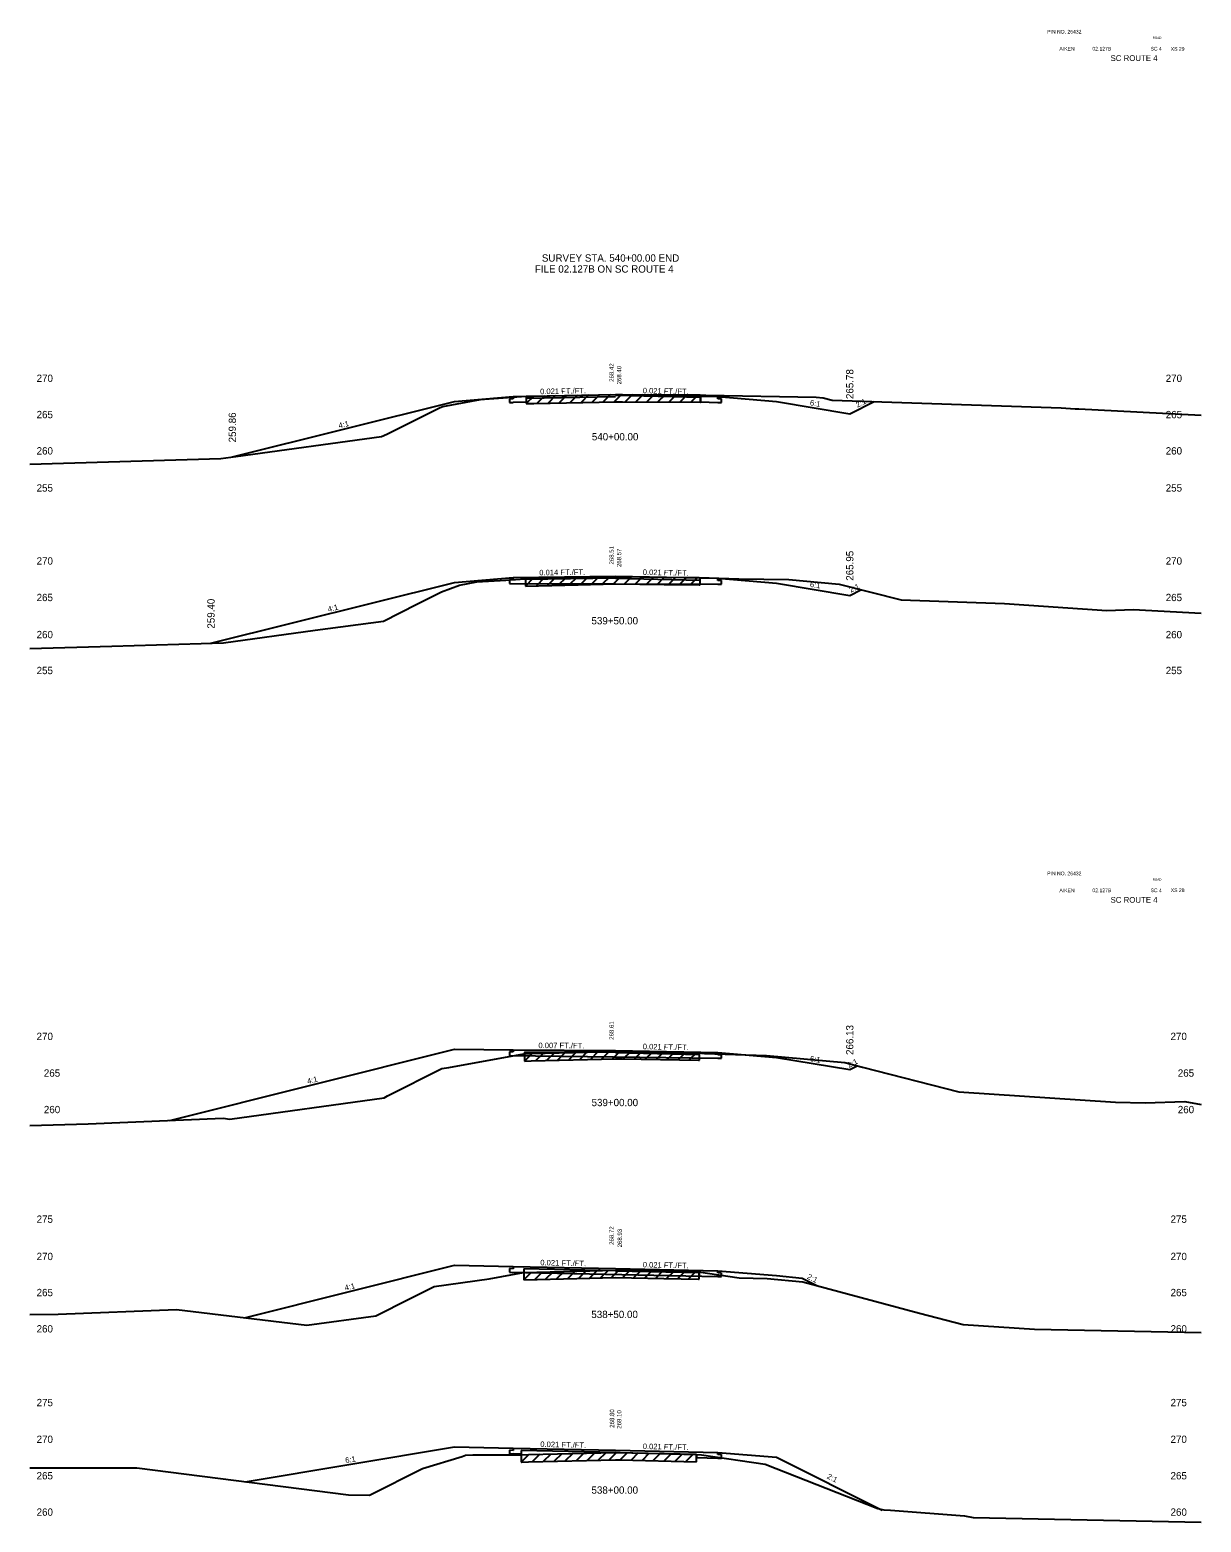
# Model space of a CAD drawing. Extents: x 883 to 1160, y 1002 to 4323.
# Drawn here: x 1000 to 1160, y 4119.3 to 4323.2 of the extents above; entities that cross this region are included whole.
import ezdxf

# ---------------------------------------------------------------- set-up
doc = ezdxf.new("R2010")
doc.units = 0
for name, color, linetype in [('Level 1', 7, 'Continuous'), ('Level 10', 7, 'Continuous'), ('Level 11', 7, 'Continuous'), ('Level 12', 7, 'Continuous'), ('Level 3', 7, 'Continuous'), ('Level 32', 7, 'Continuous'), ('Level 33', 7, 'Continuous'), ('Level 53', 7, 'Continuous'), ('Level 59', 7, 'Continuous'), ('Level 6', 7, 'Continuous'), ('Level 60', 7, 'Continuous'), ('Level 61', 7, 'Continuous'), ('Level 7', 7, 'Continuous')]:
    doc.layers.add(name, color=color, linetype=linetype)

msp = doc.modelspace()

# ---------------------------------------------------------------- linework, layer by layer
at = {"layer": 'Level 11'}
for p, q in [((1066, 4272.81), (1065.5, 4272.8)), ((1065.5, 4272.8), (1065.5, 4272.32)), ((1065.5, 4272.32), (1066, 4272.33)), ((1066, 4273.11), (1066, 4272.81)), ((1094, 4272.81), (1094, 4273.11)), ((1094.5, 4272.8), (1094, 4272.81)), ((1094, 4272.33), (1094.5, 4272.32)), ((1094.5, 4272.32), (1094.5, 4272.8)), ((1066, 4248.08), (1065.5, 4248.07)), ((1065.5, 4248.07), (1065.5, 4247.59)), ((1066, 4248.38), (1066, 4248.08)), ((1094, 4247.98), (1094, 4248.28)), ((1094.5, 4247.97), (1094, 4247.98)), ((1094, 4247.5), (1094.5, 4247.49)), ((1094.5, 4247.49), (1094.5, 4247.97)), ((1066, 4183.54), (1065.5, 4183.55)), ((1065.5, 4183.55), (1065.5, 4183.07)), ((1066, 4183.84), (1066, 4183.54)), ((1094, 4183.16), (1094, 4183.46)), ((1094.5, 4183.15), (1094, 4183.16)), ((1094, 4182.68), (1094.5, 4182.67)), ((1094.5, 4182.67), (1094.5, 4183.15)), ((1066, 4153.92), (1065.5, 4153.93)), ((1065.5, 4153.93), (1065.5, 4153.45)), ((1066, 4154.22), (1066, 4153.92)), ((1094, 4153.33), (1094, 4153.63)), ((1094.5, 4153.32), (1094, 4153.33)), ((1094, 4152.85), (1094.5, 4152.84)), ((1094.5, 4152.84), (1094.5, 4153.32)), ((1066, 4129.09), (1065.5, 4129.1)), ((1065.5, 4129.1), (1065.5, 4128.62)), ((1065.5, 4128.62), (1066, 4128.61)), ((1066, 4129.39), (1066, 4129.09)), ((1094, 4128.51), (1094, 4128.81)), ((1094.5, 4128.5), (1094, 4128.51)), ((1094.5, 4128.02), (1094.5, 4128.5)), ((1094, 4128.03), (1094.5, 4128.02))]:
    msp.add_line(p, q, dxfattribs=at)
at = {"layer": 'Level 12'}
for p, q in [((1067.8, 4273.16), (1067.8, 4272.37)), ((1091.61, 4273.35), (1091.61, 4272.38)), ((1067.8, 4272.37), (1066, 4272.33)), ((1091.61, 4272.38), (1094, 4272.33)), ((1065.5, 4247.59), (1094, 4247.5)), ((1065.5, 4183.07), (1094, 4182.68)), ((1065.5, 4153.45), (1094, 4152.85)), ((1067.46, 4153.4), (1067.46, 4153.41)), ((1091.41, 4153.48), (1091.41, 4152.91)), ((1067.13, 4128.59), (1066, 4128.61)), ((1067.13, 4128.49), (1067.13, 4128.59)), ((1091.08, 4128.54), (1091.08, 4128.09)), ((1091.08, 4128.09), (1094, 4128.03))]:
    msp.add_line(p, q, dxfattribs=at)
at = {"layer": 'Level 53'}
for p, q in [((1080, 4273.29), (1091.61, 4273.05)), ((1080, 4273.1), (1067.8, 4272.85)), ((1080, 4248.28), (1067.69, 4248.1)), ((1080, 4248.28), (1091.55, 4248.03)), ((1080, 4183.45), (1067.57, 4183.53)), ((1067.57, 4183.53), (1067.57, 4183.29)), ((1080, 4183.45), (1091.48, 4183.21)), ((1080, 4153.63), (1067.46, 4153.89)), ((1067.46, 4153.89), (1067.46, 4153.4)), ((1080, 4153.63), (1091.41, 4153.39)), ((1080, 4128.8), (1067.13, 4129.07)), ((1067.13, 4129.07), (1067.13, 4128.49)), ((1080, 4128.8), (1091.08, 4128.57)), ((1091.08, 4128.57), (1091.08, 4128.54))]:
    msp.add_line(p, q, dxfattribs=at)
at = {"layer": 'Level 59'}
for p, q in [((1066, 4273.11), (1080, 4273.4)), ((1080, 4273.4), (1094, 4273.11)), ((1066, 4248.38), (1080, 4248.58)), ((1080, 4248.58), (1094, 4248.28)), ((1066, 4183.84), (1080, 4183.75)), ((1080, 4183.75), (1094, 4183.46)), ((1066, 4154.22), (1080, 4153.93)), ((1080, 4153.93), (1094, 4153.63)), ((1066, 4129.39), (1080, 4129.1)), ((1080, 4129.1), (1094, 4128.81))]:
    msp.add_line(p, q, dxfattribs=at)
at = {"layer": 'Level 6'}
for p, q in [((1058, 4272.44), (1066, 4273.11)), ((1094, 4273.11), (1102, 4272.44)), ((1058, 4247.71), (1066, 4248.38)), ((1094, 4248.28), (1102, 4247.62)), ((1058, 4183.9), (1066, 4183.84)), ((1094, 4183.46), (1102, 4182.79)), ((1058, 4154.38), (1066, 4154.22)), ((1094, 4153.63), (1102, 4152.97)), ((1102, 4152.97), (1105.5, 4152.62)), ((1058, 4129.56), (1066, 4129.39)), ((1094, 4128.81), (1102, 4128.14))]:
    msp.add_line(p, q, dxfattribs=at)
at = {"layer": 'Level 60'}
for p, q in [((1062.12, 4272.78), (1067.8, 4273.16)), ((1067.8, 4273.16), (1068.85, 4273.19)), ((1068.85, 4273.19), (1080.02, 4273.42)), ((1080.02, 4273.42), (1080.96, 4273.4)), ((1080.96, 4273.4), (1091.56, 4273.35)), ((1091.56, 4273.35), (1092.33, 4273.32)), ((1092.33, 4273.32), (1107.41, 4273.03)), ((1048.75, 4268), (1056.03, 4271.64)), ((1056.03, 4271.64), (1056.4, 4271.78)), ((1056.4, 4271.78), (1061.54, 4272.74)), ((1061.54, 4272.74), (1062.12, 4272.78)), ((1107.41, 4273.03), (1108.39, 4272.94)), ((1108.39, 4272.94), (1109.59, 4272.64)), ((1109.59, 4272.64), (1140.87, 4271.57)), ((1140.87, 4271.57), (1142.8, 4271.44)), ((1142.8, 4271.44), (1143.3, 4271.46)), ((1143.3, 4271.46), (1160, 4270.59)), ((1028.15, 4264.92), (1048.05, 4267.64)), ((1048.05, 4267.64), (1048.75, 4268)), ((1000, 4263.89), (1026.08, 4264.64)), ((1026.08, 4264.64), (1028.15, 4264.92)), ((1056.25, 4246.44), (1058.7, 4247.36)), ((1058.7, 4247.36), (1061.06, 4247.8)), ((1061.06, 4247.8), (1065.03, 4248.04)), ((1065.03, 4248.04), (1067.64, 4248.22)), ((1067.64, 4248.22), (1074.91, 4248.41)), ((1074.91, 4248.41), (1080, 4248.51)), ((1080, 4248.51), (1086.64, 4248.42)), ((1086.64, 4248.42), (1091.45, 4248.39)), ((1091.45, 4248.39), (1096.85, 4248.23)), ((1096.85, 4248.23), (1103.68, 4248.1)), ((1103.68, 4248.1), (1110.56, 4247.48)), ((1110.56, 4247.48), (1119.02, 4245.32)), ((1048.3, 4242.44), (1052.88, 4244.75)), ((1052.88, 4244.75), (1056.25, 4246.44)), ((1119.02, 4245.32), (1133.13, 4244.84)), ((1133.13, 4244.84), (1147.14, 4243.9)), ((1147.14, 4243.9), (1150.72, 4244.01)), ((1150.72, 4244.01), (1160, 4243.53)), ((1026.43, 4239.45), (1038.97, 4241.17)), ((1038.97, 4241.17), (1048.3, 4242.44)), ((1000, 4238.69), (1011.18, 4239.01)), ((1011.18, 4239.01), (1026.43, 4239.45)), ((1068.47, 4183.31), (1080, 4183.61)), ((1080, 4183.61), (1080.91, 4183.59)), ((1080.91, 4183.59), (1091.36, 4183.44)), ((1091.36, 4183.44), (1092.16, 4183.32)), ((1056.28, 4181.29), (1057.22, 4181.42)), ((1057.22, 4181.42), (1067.49, 4183.29)), ((1067.49, 4183.29), (1068.47, 4183.31)), ((1092.16, 4183.32), (1100.61, 4183.07)), ((1100.61, 4183.07), (1111.34, 4182.1)), ((1111.34, 4182.1), (1113.72, 4181.45)), ((1113.72, 4181.45), (1126.88, 4178.09)), ((1048.87, 4177.53), (1056.28, 4181.29)), ((1027.33, 4174.36), (1048.39, 4177.28)), ((1048.39, 4177.28), (1048.87, 4177.53)), ((1126.88, 4178.09), (1148.31, 4176.67)), ((1148.31, 4176.67), (1152.35, 4176.59)), ((1152.35, 4176.59), (1157.77, 4176.76)), ((1157.77, 4176.76), (1160, 4176.35)), ((1000, 4173.49), (1007.96, 4173.72)), ((1007.96, 4173.72), (1026.4, 4174.47)), ((1026.4, 4174.47), (1027.33, 4174.36)), ((1062.74, 4152.54), (1067.43, 4153.4)), ((1067.43, 4153.4), (1074.74, 4153.58)), ((1074.74, 4153.58), (1080, 4153.72)), ((1080, 4153.72), (1086.59, 4153.56)), ((1086.59, 4153.56), (1091.34, 4153.49)), ((1091.34, 4153.49), (1096.88, 4152.69)), ((1051.84, 4149.78), (1055.21, 4151.49)), ((1055.21, 4151.49), (1062.74, 4152.54)), ((1096.88, 4152.69), (1100.71, 4152.58)), ((1100.71, 4152.58), (1105.58, 4152.14)), ((1105.58, 4152.14), (1121.52, 4147.82)), ((1047.27, 4147.49), (1051.84, 4149.78)), ((1000, 4147.66), (1003.85, 4147.69)), ((1003.85, 4147.69), (1020.04, 4148.35)), ((1020.04, 4148.35), (1037.82, 4146.18)), ((1037.82, 4146.18), (1047.27, 4147.49)), ((1121.52, 4147.82), (1127.5, 4146.29)), ((1127.5, 4146.29), (1137.24, 4145.65)), ((1137.24, 4145.65), (1160, 4145.19)), ((1059.06, 4128.26), (1059.51, 4128.44)), ((1059.51, 4128.44), (1060.49, 4128.46)), ((1060.49, 4128.46), (1067.15, 4128.49)), ((1067.15, 4128.49), (1068.13, 4128.52)), ((1068.13, 4128.52), (1080, 4128.8)), ((1080, 4128.8), (1080.64, 4128.79)), ((1080.64, 4128.79), (1091.05, 4128.54)), ((1091.05, 4128.54), (1091.77, 4128.47)), ((1091.77, 4128.47), (1100.46, 4127.21)), ((1000, 4126.69), (1013.54, 4126.69)), ((1013.54, 4126.69), (1014.6, 4126.68)), ((1014.6, 4126.68), (1043.54, 4122.99)), ((1046.38, 4122.97), (1053.63, 4126.6)), ((1053.63, 4126.6), (1059.06, 4128.26)), ((1100.46, 4127.21), (1115.83, 4121.16)), ((1043.54, 4122.99), (1046.38, 4122.97)), ((1115.83, 4121.16), (1116.65, 4120.97)), ((1116.65, 4120.97), (1117.58, 4120.93)), ((1117.58, 4120.93), (1127.66, 4120.15)), ((1127.66, 4120.15), (1128.84, 4119.9)), ((1128.84, 4119.9), (1160, 4119.27))]:
    msp.add_line(p, q, dxfattribs=at)
at = {"layer": 'Level 61'}
for p, q in [((1068.83, 4273.19), (1067.8, 4272.16)), ((1067.8, 4273.16), (1067.8, 4272.16)), ((1070.32, 4273.22), (1069.3, 4272.2)), ((1071.82, 4273.25), (1070.8, 4272.23)), ((1073.32, 4273.28), (1072.3, 4272.26)), ((1074.82, 4273.31), (1073.8, 4272.29)), ((1076.32, 4273.34), (1075.3, 4272.32)), ((1077.82, 4273.37), (1076.8, 4272.35)), ((1079.32, 4273.4), (1078.3, 4272.38)), ((1080.8, 4273.4), (1079.8, 4272.41)), ((1082.3, 4273.4), (1081.3, 4272.4)), ((1083.8, 4273.39), (1082.8, 4272.39)), ((1085.3, 4273.38), (1084.3, 4272.39)), ((1086.8, 4273.37), (1085.8, 4272.38)), ((1088.3, 4273.36), (1087.3, 4272.37)), ((1089.8, 4273.36), (1088.8, 4272.36)), ((1091.3, 4273.35), (1090.3, 4272.35)), ((1091.61, 4272.35), (1091.61, 4273.35)), ((1067.8, 4272.16), (1068.85, 4272.19)), ((1068.85, 4272.19), (1080.02, 4272.42)), ((1080.02, 4272.42), (1080.96, 4272.4)), ((1080.96, 4272.4), (1091.56, 4272.35)), ((1091.56, 4272.35), (1091.61, 4272.35)), ((1068.71, 4248.25), (1067.69, 4247.22)), ((1067.69, 4248.22), (1067.69, 4247.22)), ((1067.69, 4247.22), (1074.91, 4247.41)), ((1070.21, 4248.29), (1069.19, 4247.26)), ((1071.71, 4248.32), (1070.69, 4247.3)), ((1073.21, 4248.36), (1072.19, 4247.34)), ((1074.71, 4248.4), (1073.69, 4247.38)), ((1074.91, 4247.41), (1080, 4247.51)), ((1076.21, 4248.43), (1075.19, 4247.41)), ((1077.71, 4248.46), (1076.69, 4247.44)), ((1079.21, 4248.49), (1078.19, 4247.47)), ((1080.68, 4248.5), (1079.69, 4247.5)), ((1080, 4247.51), (1086.64, 4247.42)), ((1082.17, 4248.48), (1081.19, 4247.49)), ((1083.67, 4248.46), (1082.69, 4247.47)), ((1085.17, 4248.44), (1084.19, 4247.45)), ((1086.67, 4248.42), (1085.69, 4247.43)), ((1086.64, 4247.42), (1091.45, 4247.39)), ((1088.18, 4248.41), (1087.19, 4247.41)), ((1089.68, 4248.4), (1088.69, 4247.41)), ((1091.18, 4248.39), (1090.19, 4247.4)), ((1091.45, 4247.39), (1091.55, 4247.39)), ((1091.55, 4247.39), (1091.55, 4248.39)), ((1071.6, 4183.39), (1070.57, 4182.37)), ((1073.1, 4183.43), (1072.07, 4182.4)), ((1074.6, 4183.47), (1073.57, 4182.44)), ((1076.1, 4183.51), (1075.07, 4182.48)), ((1077.6, 4183.55), (1076.57, 4182.52)), ((1079.1, 4183.58), (1078.07, 4182.56)), ((1080.57, 4183.59), (1079.57, 4182.6)), ((1082.06, 4183.57), (1081.07, 4182.58)), ((1083.56, 4183.55), (1082.57, 4182.56)), ((1085.06, 4183.53), (1084.07, 4182.54)), ((1086.56, 4183.51), (1085.57, 4182.52)), ((1088.06, 4183.49), (1087.07, 4182.5)), ((1089.56, 4183.46), (1088.57, 4182.48)), ((1091.06, 4183.44), (1090.07, 4182.46)), ((1091.48, 4182.42), (1091.48, 4183.42)), ((1068.6, 4183.32), (1067.57, 4182.29)), ((1067.57, 4183.29), (1067.57, 4182.29)), ((1067.57, 4182.29), (1068.47, 4182.31)), ((1068.47, 4182.31), (1080, 4182.61)), ((1070.1, 4183.35), (1069.07, 4182.33)), ((1080, 4182.61), (1080.91, 4182.59)), ((1080.91, 4182.59), (1091.36, 4182.44)), ((1091.36, 4182.44), (1091.48, 4182.42)), ((1068.49, 4153.42), (1067.46, 4152.4)), ((1067.46, 4153.4), (1067.46, 4152.4)), ((1069.99, 4153.46), (1068.96, 4152.44)), ((1071.49, 4153.5), (1070.46, 4152.47)), ((1072.99, 4153.54), (1071.96, 4152.51)), ((1074.49, 4153.58), (1073.46, 4152.55)), ((1075.99, 4153.62), (1074.96, 4152.59)), ((1077.49, 4153.65), (1076.46, 4152.63)), ((1078.99, 4153.69), (1077.96, 4152.67)), ((1080.46, 4153.71), (1079.46, 4152.7)), ((1081.94, 4153.67), (1080.96, 4152.69)), ((1083.44, 4153.64), (1082.46, 4152.66)), ((1084.94, 4153.6), (1083.96, 4152.62)), ((1086.44, 4153.56), (1085.46, 4152.59)), ((1087.95, 4153.54), (1086.96, 4152.56)), ((1089.45, 4153.52), (1088.46, 4152.53)), ((1090.95, 4153.5), (1089.96, 4152.51)), ((1091.41, 4152.48), (1091.41, 4153.48)), ((1067.46, 4152.4), (1074.74, 4152.58)), ((1074.74, 4152.58), (1080, 4152.72)), ((1080, 4152.72), (1086.59, 4152.56)), ((1086.59, 4152.56), (1091.34, 4152.49)), ((1091.34, 4152.49), (1091.41, 4152.48)), ((1068.15, 4128.52), (1067.13, 4127.49)), ((1067.13, 4128.49), (1067.13, 4127.49)), ((1069.66, 4128.55), (1068.63, 4127.53)), ((1071.16, 4128.59), (1070.13, 4127.56)), ((1072.66, 4128.63), (1071.63, 4127.6)), ((1074.16, 4128.66), (1073.13, 4127.64)), ((1075.66, 4128.7), (1074.63, 4127.67)), ((1077.16, 4128.74), (1076.13, 4127.71)), ((1078.66, 4128.77), (1077.63, 4127.75)), ((1080.15, 4128.8), (1079.13, 4127.78)), ((1081.61, 4128.77), (1080.63, 4127.79)), ((1083.11, 4128.73), (1082.13, 4127.76)), ((1084.61, 4128.7), (1083.63, 4127.72)), ((1086.11, 4128.66), (1085.13, 4127.69)), ((1087.61, 4128.63), (1086.63, 4127.65)), ((1089.11, 4128.59), (1088.13, 4127.61)), ((1090.61, 4128.55), (1089.63, 4127.58)), ((1091.08, 4127.54), (1091.08, 4128.54)), ((1067.13, 4127.49), (1067.15, 4127.49)), ((1067.15, 4127.49), (1068.13, 4127.52)), ((1068.13, 4127.52), (1080, 4127.8)), ((1080, 4127.8), (1080.64, 4127.79)), ((1080.64, 4127.79), (1091.05, 4127.54)), ((1091.05, 4127.54), (1091.08, 4127.54))]:
    msp.add_line(p, q, dxfattribs=at)
at = {"layer": 'Level 7'}
for p, q in [((1027.66, 4264.86), (1058, 4272.44)), ((1102, 4272.44), (1112, 4270.78)), ((1112, 4270.78), (1115.33, 4272.44)), ((1024.74, 4239.4), (1058, 4247.71)), ((1102, 4247.62), (1112, 4245.95)), ((1112, 4245.95), (1113.53, 4246.72)), ((1019.1, 4174.17), (1058, 4183.9)), ((1102, 4182.79), (1112, 4181.13)), ((1112, 4181.13), (1113.03, 4181.64)), ((1029.33, 4147.22), (1058, 4154.38)), ((1105.5, 4152.62), (1107.5, 4151.62)), ((1029.42, 4124.79), (1058, 4129.56)), ((1102, 4128.14), (1116.43, 4120.93))]:
    msp.add_line(p, q, dxfattribs=at)

# ---------------------------------------------------------------- texts
at = {"layer": 'Level 1'}
for s, height, p in [('PIN NO. 26432', 0.5, (1138.97, 4322.74)), ('AIKEN', 0.5, (1140.64, 4320.42)), ('02.127B', 0.5, (1145.15, 4320.42)), ('SC 4', 0.5, (1153.09, 4320.42)), ('XS 29', 0.5, (1155.85, 4320.39)), ('SC ROUTE 4', 0.8, (1147.63, 4318.98)), ('SURVEY STA. 540+00.00 END', 1, (1069.94, 4291.56)), ('FILE 02.127B ON SC ROUTE 4 ', 1, (1068.99, 4290.06)), ('540+00.00', 1, (1076.77, 4267.13)), ('539+50.00', 1, (1076.72, 4241.98)), ('PIN NO. 26432', 0.5, (1138.97, 4207.69)), ('AIKEN', 0.5, (1140.64, 4205.38)), ('02.127B', 0.5, (1145.15, 4205.38)), ('SC 4', 0.5, (1153.09, 4205.38)), ('XS 28', 0.5, (1155.85, 4205.4)), ('SC ROUTE 4', 0.8, (1147.63, 4203.93)), ('539+00.00', 1, (1076.73, 4176.13)), ('538+50.00', 1, (1076.7, 4147.17)), ('538+00.00', 1, (1076.72, 4123.16))]:
    msp.add_text(s, height=height, dxfattribs=at).set_placement(p)
at = {"layer": 'Level 10'}
for s, p in [('268.42', (1079.76, 4275.13)), ('268.51', (1079.76, 4250.16)), ('268.61', (1079.76, 4185.2)), ('268.72', (1079.76, 4157.17)), ('268.80', (1079.82, 4132.17))]:
    msp.add_text(s, height=0.6, rotation=90, dxfattribs=at).set_placement(p)
at = {"layer": 'Level 3'}
for s, height, p in [('ROAD', 0.3, (1153.38, 4322.01)), (' 270', 1, (1000.55, 4275.12)), (' 270', 1, (1154.79, 4275.12)), (' 265', 1, (1000.55, 4270.16)), (' 265', 1, (1154.79, 4270.16)), (' 260', 1, (1000.55, 4265.2)), (' 260', 1, (1154.79, 4265.2)), (' 255', 1, (1000.55, 4260.13)), (' 255', 1, (1154.79, 4260.13)), (' 270', 1, (1000.55, 4250.15)), (' 270', 1, (1154.79, 4250.15)), (' 265', 1, (1000.55, 4245.16)), (' 265', 1, (1154.79, 4245.16)), (' 260', 1, (1000.55, 4240.09)), (' 260', 1, (1154.79, 4240.09)), (' 255', 1, (1000.55, 4235.18)), (' 255', 1, (1154.79, 4235.18)), ('ROAD', 0.3, (1153.38, 4206.96)), (' 270', 1, (1000.55, 4185.17)), (' 270', 1, (1155.45, 4185.17)), (' 265', 1, (1001.54, 4180.16)), (' 265', 1, (1156.44, 4180.16)), (' 260', 1, (1001.54, 4175.17)), (' 260', 1, (1156.44, 4175.17)), (' 275', 1, (1000.55, 4160.19)), (' 275', 1, (1155.45, 4160.19)), (' 270', 1, (1000.55, 4155.09)), (' 270', 1, (1155.45, 4155.09)), (' 265', 1, (1000.55, 4150.16)), (' 265', 1, (1155.45, 4150.16)), (' 260', 1, (1000.55, 4145.2)), (' 260', 1, (1155.45, 4145.2)), (' 275', 1, (1000.55, 4135.12)), (' 275', 1, (1155.45, 4135.12)), (' 270', 1, (1000.55, 4130.1)), (' 270', 1, (1155.45, 4130.1)), (' 265', 1, (1000.55, 4125.12)), (' 265', 1, (1155.45, 4125.12)), (' 260', 1, (1000.55, 4120.15)), (' 260', 1, (1155.45, 4120.15))]:
    msp.add_text(s, height=height, dxfattribs=at).set_placement(p)
at = {"layer": 'Level 32'}
for s, rotation, p in [('0.021 FT./FT.', 1.1916, (1069.71, 4273.44)), ('0.021 FT./FT.', 358.8084, (1083.72, 4273.57)), ('6:1', 350.5377, (1106.52, 4271.94)), ('2:1', 26.5651, (1113.05, 4271.58)), ('4:1', 14.0362, (1042.26, 4268.76)), ('0.014 FT./FT.', 0.8054, (1069.59, 4248.68)), ('0.021 FT./FT.', 358.8084, (1083.72, 4248.75)), ('6:1', 350.5377, (1106.52, 4247.12)), ('2:1', 26.5651, (1112.15, 4246.3)), ('4:1', 14.0362, (1040.79, 4243.67)), ('0.007 FT./FT.', 359.6137, (1069.47, 4184.07)), ('0.021 FT./FT.', 358.8084, (1083.72, 4183.92)), ('6:1', 350.5377, (1106.52, 4182.29)), ('2:1', 26.5651, (1111.9, 4181.35)), ('4:1', 14.0362, (1037.97, 4179.15)), ('0.021 FT./FT.', 358.8084, (1069.72, 4154.39)), ('0.021 FT./FT.', 358.8084, (1083.72, 4154.1)), ('2:1', 333.435, (1106.1, 4152.59)), ('4:1', 14.0362, (1043.09, 4150.91)), ('0.021 FT./FT.', 358.8084, (1069.72, 4129.56)), ('0.021 FT./FT.', 358.8084, (1083.72, 4129.27)), ('6:1', 9.4623, (1043.14, 4127.34)), ('2:1', 333.435, (1108.81, 4125.3))]:
    msp.add_text(s, height=0.75, rotation=rotation, dxfattribs=at).set_placement(p)
at = {"layer": 'Level 33'}
for s, p in [('265.78', (1112.5, 4272.78)), ('259.86', (1028.16, 4266.86)), ('265.95', (1112.5, 4247.95)), ('259.40', (1025.24, 4241.4)), ('266.13', (1112.5, 4183.13))]:
    msp.add_text(s, height=1, rotation=90, dxfattribs=at).set_placement(p)
at = {"layer": 'Level 59'}
for s, p in [(' 268.40', (1080.79, 4274.55)), (' 268.57', (1080.79, 4249.58)), (' 268.93', (1080.88, 4156.6)), (' 269.10', (1080.8, 4131.81))]:
    msp.add_text(s, height=0.6, rotation=90, dxfattribs=at).set_placement(p)

doc.saveas('drawing.dxf')
